// Mitsubishi GX Works2 project: 称重例程   PLC: FX3U/FX3UC

PROGRAM MAIN
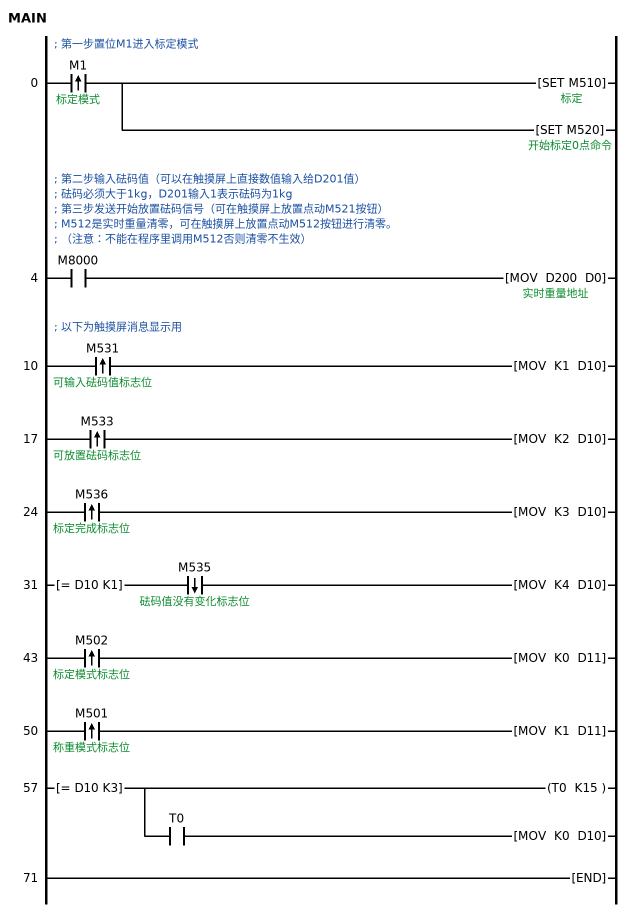
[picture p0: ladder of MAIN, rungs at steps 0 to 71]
; 第一步置位M1进入标定模式
0     LDP     M1  ; 标定模式
      SET     M510  ; 标定
      SET     M520  ; 开始标定0点命令
; 第二步输入砝码值（可以在触摸屏上直接数值输入给D201值）
; 砝码必须大于1kg，D201输入1表示砝码为1kg
; 第三步发送开始放置砝码信号（可在触摸屏上放置点动M521按钮）
; M512是实时重量清零，可在触摸屏上放置点动M512按钮进行清零。
; （注意：不能在程序里调用M512否则清零不生效）
4     LD      M8000
      MOV     D200 D0  ; 实时重量地址
; 以下为触摸屏消息显示用
10    LDP     M531  ; 可输入砝码值标志位
      MOV     K1 D10
17    LDP     M533  ; 可放置砝码标志位
      MOV     K2 D10
24    LDP     M536  ; 标定完成标志位
      MOV     K3 D10
31    LD=     D10 K1
      ANDF    M535  ; 砝码值没有变化标志位
      MOV     K4 D10
43    LDP     M502  ; 标定模式标志位
      MOV     K0 D11
50    LDP     M501  ; 称重模式标志位
      MOV     K1 D11
57    LD=     D10 K3
      OUT     T0 K15
      AND     T0
      MOV     K0 D10
71    END
END_PROGRAM

// device comments not shown above
M512  ; 清零
M521  ; 开始放置砝码
D201  ; 标定砝码值
M2  ; 输入砝码值
M3  ; 开始放置砝码
